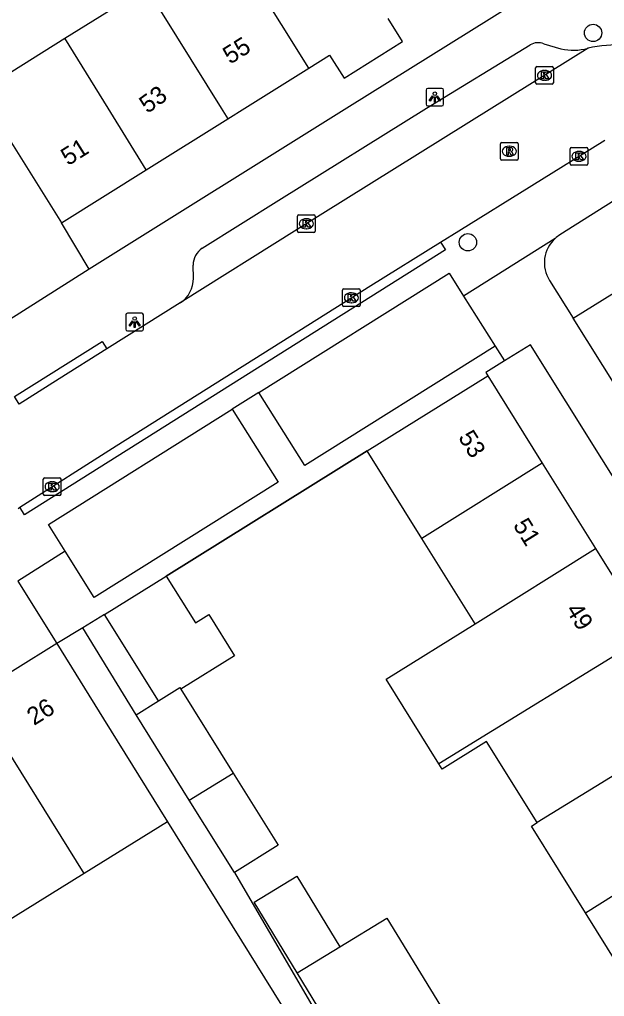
# Model space of a CAD drawing. Extents: x 157767 to 159171, y 387842 to 389425.
# Drawn here: x 158417.9 to 158451, y 388199.8 to 388255 of the extents above; entities that cross this region are included whole.
import ezdxf

# ---------------------------------------------------------------- set-up
doc = ezdxf.new("R2010")
doc.units = 0
for name, color, linetype in [('IMGEO_Boom', 7, 'Continuous'), ('IMGEO_Groenvoorziening', 7, 'Continuous'), ('IMGEO_Kolk', 7, 'Continuous'), ('IMGEO_Lichtpunt', 7, 'Continuous'), ('IMGEO_Muur', 7, 'Continuous'), ('IMGEO_Pand', 7, 'Continuous'), ('IMGEO_Pand_nummerreeks', 7, 'Continuous'), ('IMGEO_Rijbaan_lokaal_open', 7, 'Continuous'), ('IMGEO_Rioolput', 7, 'Continuous'), ('IMGEO_Voetpad_open', 7, 'Continuous')]:
    doc.layers.add(name, color=color, linetype=linetype)

msp = doc.modelspace()

# ---------------------------------------------------------------- linework, layer by layer
at = {"layer": 'IMGEO_Boom'}
for centre in [(158450.319, 388254.256), (158443.243, 388242.419)]:
    msp.add_circle(centre, 0.489, dxfattribs=at)
at = {"layer": 'IMGEO_Groenvoorziening'}
msp.add_lwpolyline([(158449.191, 388238.128), (158453.713, 388240.945), (158464.018, 388232.359)], dxfattribs=at)
at = {"layer": 'IMGEO_Kolk'}
for p, q in [((158447.072, 388251.429), (158447.072, 388252.281)), ((158447.147, 388252.355), (158447.999, 388252.355)), ((158447.56, 388252.135), (158447.585, 388252.135)), ((158448.073, 388252.281), (158448.073, 388251.429)), ((158447.583, 388251.575), (158447.558, 388251.575)), ((158447.999, 388251.355), (158447.147, 388251.355)), ((158449.02, 388246.852), (158449.02, 388247.704)), ((158449.095, 388247.778), (158449.947, 388247.778)), ((158449.508, 388247.558), (158449.533, 388247.558)), ((158450.021, 388247.704), (158450.021, 388246.852)), ((158449.531, 388246.998), (158449.506, 388246.998)), ((158449.947, 388246.778), (158449.095, 388246.778)), ((158433.622, 388243.041), (158433.622, 388243.893)), ((158433.697, 388243.967), (158434.549, 388243.967)), ((158434.11, 388243.747), (158434.135, 388243.747)), ((158434.623, 388243.893), (158434.623, 388243.041)), ((158434.133, 388243.187), (158434.108, 388243.187)), ((158434.549, 388242.967), (158433.697, 388242.967)), ((158436.242, 388239.783), (158437.094, 388239.783)), ((158436.167, 388238.857), (158436.167, 388239.709)), ((158436.655, 388239.563), (158436.68, 388239.563)), ((158437.168, 388239.709), (158437.168, 388238.857)), ((158437.094, 388238.783), (158436.242, 388238.783)), ((158436.678, 388239.003), (158436.653, 388239.003)), ((158419.264, 388228.177), (158419.264, 388229.029)), ((158419.339, 388229.103), (158420.191, 388229.103)), ((158419.752, 388228.883), (158419.777, 388228.883)), ((158420.265, 388229.029), (158420.265, 388228.177)), ((158419.775, 388228.323), (158419.75, 388228.323)), ((158420.191, 388228.103), (158419.339, 388228.103))]:
    msp.add_line(p, q, dxfattribs=at)
for points in [[(158447.072, 388251.429), (158447.072, 388252.281)], [(158447.147, 388252.355), (158447.999, 388252.355)], [(158447.393, 388252.055), (158447.516, 388252.055), (158447.516, 388251.904), (158447.646, 388252.055), (158447.81, 388252.055), (158447.664, 388251.904), (158447.817, 388251.655), (158447.665, 388251.655), (158447.58, 388251.819), (158447.516, 388251.752), (158447.516, 388251.655), (158447.393, 388251.655), (158447.393, 388252.055)], [(158448.073, 388252.281), (158448.073, 388251.429)], [(158447.999, 388251.355), (158447.147, 388251.355)], [(158449.02, 388246.852), (158449.02, 388247.704)], [(158449.095, 388247.778), (158449.947, 388247.778)], [(158450.021, 388247.704), (158450.021, 388246.852)], [(158449.341, 388247.478), (158449.464, 388247.478), (158449.464, 388247.327), (158449.594, 388247.478), (158449.758, 388247.478), (158449.612, 388247.327), (158449.765, 388247.078), (158449.613, 388247.078), (158449.528, 388247.242), (158449.464, 388247.175), (158449.464, 388247.078), (158449.341, 388247.078), (158449.341, 388247.478)], [(158449.947, 388246.778), (158449.095, 388246.778)], [(158433.622, 388243.041), (158433.622, 388243.893)], [(158433.697, 388243.967), (158434.549, 388243.967)], [(158433.943, 388243.667), (158434.066, 388243.667), (158434.066, 388243.516), (158434.196, 388243.667), (158434.36, 388243.667), (158434.214, 388243.516), (158434.367, 388243.267), (158434.215, 388243.267), (158434.13, 388243.431), (158434.066, 388243.364), (158434.066, 388243.267), (158433.943, 388243.267), (158433.943, 388243.667)], [(158434.623, 388243.893), (158434.623, 388243.041)], [(158434.549, 388242.967), (158433.697, 388242.967)], [(158436.242, 388239.783), (158437.094, 388239.783)], [(158436.167, 388238.857), (158436.167, 388239.709)], [(158436.488, 388239.483), (158436.611, 388239.483), (158436.611, 388239.332), (158436.741, 388239.483), (158436.905, 388239.483), (158436.759, 388239.332), (158436.912, 388239.083), (158436.76, 388239.083), (158436.675, 388239.247), (158436.611, 388239.18), (158436.611, 388239.083), (158436.488, 388239.083), (158436.488, 388239.483)], [(158437.168, 388239.709), (158437.168, 388238.857)], [(158437.094, 388238.783), (158436.242, 388238.783)], [(158419.264, 388228.177), (158419.264, 388229.029)], [(158419.339, 388229.103), (158420.191, 388229.103)], [(158419.585, 388228.803), (158419.708, 388228.803), (158419.708, 388228.652), (158419.838, 388228.803), (158420.002, 388228.803), (158419.856, 388228.652), (158420.009, 388228.403), (158419.857, 388228.403), (158419.772, 388228.567), (158419.708, 388228.5), (158419.708, 388228.403), (158419.585, 388228.403), (158419.585, 388228.803)], [(158420.265, 388229.029), (158420.265, 388228.177)], [(158420.191, 388228.103), (158419.339, 388228.103)]]:
    msp.add_lwpolyline(points, dxfattribs=at)
for centre, start, end in [((158447.149, 388252.279), 91.552, 178.448), ((158447.149, 388252.279), 91.552, 178.448), ((158447.997, 388252.279), 1.552, 88.448), ((158447.997, 388252.279), 1.552, 88.448), ((158447.149, 388251.431), 181.552, 268.448), ((158447.149, 388251.431), 181.552, 268.448), ((158447.997, 388251.431), 271.552, 358.448), ((158447.997, 388251.431), 271.552, 358.448), ((158449.097, 388247.702), 91.552, 178.448), ((158449.097, 388247.702), 91.552, 178.448), ((158449.945, 388247.702), 1.552, 88.448), ((158449.945, 388247.702), 1.552, 88.448), ((158449.097, 388246.854), 181.552, 268.448), ((158449.097, 388246.854), 181.552, 268.448), ((158449.945, 388246.854), 271.552, 358.448), ((158449.945, 388246.854), 271.552, 358.448), ((158433.699, 388243.891), 91.552, 178.448), ((158433.699, 388243.891), 91.552, 178.448), ((158434.547, 388243.891), 1.552, 88.448), ((158434.547, 388243.891), 1.552, 88.448), ((158433.699, 388243.043), 181.552, 268.448), ((158433.699, 388243.043), 181.552, 268.448), ((158434.547, 388243.043), 271.552, 358.448), ((158434.547, 388243.043), 271.552, 358.448), ((158436.244, 388239.707), 91.552, 178.448), ((158436.244, 388239.707), 91.552, 178.448), ((158437.092, 388239.707), 1.552, 88.448), ((158437.092, 388239.707), 1.552, 88.448), ((158436.244, 388238.859), 181.552, 268.448), ((158436.244, 388238.859), 181.552, 268.448), ((158437.092, 388238.859), 271.552, 358.448), ((158437.092, 388238.859), 271.552, 358.448), ((158419.341, 388229.027), 91.552, 178.448), ((158419.341, 388229.027), 91.552, 178.448), ((158420.189, 388229.027), 1.552, 88.448), ((158420.189, 388229.027), 1.552, 88.448), ((158419.341, 388228.179), 181.552, 268.448), ((158419.341, 388228.179), 181.552, 268.448), ((158420.189, 388228.179), 271.552, 358.448), ((158420.189, 388228.179), 271.552, 358.448)]:
    msp.add_arc(centre, 0.0765, start, end, dxfattribs=at)
for centre, major_axis, ratio, start_param, end_param in [((158447.559, 388251.855), (-0.387, 0.002), 0.722429, 4.712389, 7.853982), ((158447.584, 388251.855), (-0.39, 0.002), 0.717154, 1.570796, 4.712389), ((158449.507, 388247.278), (-0.387, 0.002), 0.722429, 4.712389, 7.853982), ((158449.532, 388247.278), (-0.39, 0.002), 0.717154, 1.570796, 4.712389), ((158434.109, 388243.467), (-0.387, 0.002), 0.722429, 4.712389, 7.853982), ((158434.134, 388243.467), (-0.39, 0.002), 0.717154, 1.570796, 4.712389), ((158436.654, 388239.283), (-0.387, 0.002), 0.722429, 4.712389, 7.853982), ((158436.679, 388239.283), (-0.39, 0.002), 0.717154, 1.570796, 4.712389), ((158419.751, 388228.603), (-0.387, 0.002), 0.722429, 4.712389, 7.853982), ((158419.776, 388228.603), (-0.39, 0.002), 0.717154, 1.570796, 4.712389)]:
    msp.add_ellipse(centre, major_axis=major_axis, ratio=ratio, start_param=start_param, end_param=end_param, dxfattribs=at)
at = {"layer": 'IMGEO_Lichtpunt'}
for p, q in [((158440.88, 388251.027), (158440.88, 388250.22)), ((158440.88, 388251.027), (158440.88, 388250.22)), ((158441.782, 388251.122), (158440.974, 388251.122)), ((158441.782, 388251.122), (158440.974, 388251.122)), ((158441.876, 388250.22), (158441.876, 388251.027)), ((158441.876, 388250.22), (158441.876, 388251.027)), ((158440.974, 388250.126), (158441.782, 388250.126)), ((158440.974, 388250.126), (158441.782, 388250.126)), ((158423.927, 388238.312), (158423.927, 388237.505)), ((158423.927, 388238.312), (158423.927, 388237.505)), ((158424.829, 388238.407), (158424.021, 388238.407)), ((158424.829, 388238.407), (158424.021, 388238.407)), ((158424.923, 388237.505), (158424.923, 388238.312)), ((158424.923, 388237.505), (158424.923, 388238.312)), ((158424.021, 388237.411), (158424.829, 388237.411)), ((158424.021, 388237.411), (158424.829, 388237.411))]:
    msp.add_line(p, q, dxfattribs=at)
for points in [[(158441.254, 388250.691), (158441.293, 388250.663), (158441.105, 388250.401), (158441.067, 388250.428), (158441.254, 388250.691)], [(158441.356, 388250.643), (158441.403, 388250.643), (158441.403, 388250.321), (158441.356, 388250.321), (158441.356, 388250.643)], [(158441.466, 388250.663), (158441.504, 388250.69), (158441.691, 388250.428), (158441.652, 388250.4), (158441.466, 388250.663)], [(158424.301, 388237.976), (158424.34, 388237.948), (158424.152, 388237.686), (158424.114, 388237.713), (158424.301, 388237.976)], [(158424.403, 388237.928), (158424.45, 388237.928), (158424.45, 388237.606), (158424.403, 388237.606), (158424.403, 388237.928)], [(158424.513, 388237.948), (158424.551, 388237.975), (158424.738, 388237.713), (158424.699, 388237.685), (158424.513, 388237.948)]]:
    msp.add_lwpolyline(points, dxfattribs=at)
for centre in [(158441.379, 388250.825), (158424.426, 388238.11)]:
    msp.add_circle(centre, 0.0994, dxfattribs=at)
for centre, start, end in [((158440.974, 388251.027), 90, 180), ((158440.974, 388251.027), 90, 180), ((158441.782, 388251.027), 0, 90), ((158441.782, 388251.027), 0, 90), ((158440.974, 388250.22), 180, 270), ((158440.974, 388250.22), 180, 270), ((158441.782, 388250.22), 270, 0), ((158441.782, 388250.22), 270, 360), ((158424.021, 388238.312), 90, 180), ((158424.021, 388238.312), 90, 180), ((158424.829, 388238.312), 0, 90), ((158424.829, 388238.312), 0, 90), ((158424.021, 388237.505), 180, 270), ((158424.021, 388237.505), 180, 270), ((158424.829, 388237.505), 270, 0), ((158424.829, 388237.505), 270, 360)]:
    msp.add_arc(centre, 0.0946, start, end, dxfattribs=at)
at = {"layer": 'IMGEO_Muur'}
msp.add_lwpolyline([(158426.209, 388223.555), (158437.564, 388230.626)], dxfattribs=at)
at = {"layer": 'IMGEO_Pand'}
for points in [[(158434.257, 388252.266), (158429.634, 388259.687)], [(158420.487, 388253.952), (158425.074, 388256.828)], [(158425.074, 388256.828), (158429.309, 388250), (158429.683, 388249.398)], [(158434.257, 388252.266), (158435.432, 388253.003), (158436.25, 388251.698), (158439.554, 388253.77), (158438.736, 388255.075)], [(158415.649, 388250.918), (158420.487, 388253.952)], [(158425.084, 388246.515), (158422.93, 388250), (158420.487, 388253.952)], [(158429.683, 388249.398), (158430.642, 388250), (158434.257, 388252.266)], [(158415.649, 388250.918), (158416.225, 388250), (158420.293, 388243.511)], [(158425.084, 388246.515), (158429.683, 388249.398)], [(158420.293, 388243.511), (158425.084, 388246.515)], [(158437.564, 388230.626), (158444.372, 388234.867)], [(158444.372, 388234.867), (158447.444, 388229.936)], [(158440.642, 388225.684), (158437.564, 388230.626)], [(158447.444, 388229.936), (158440.642, 388225.684)], [(158447.444, 388229.936), (158450.447, 388225.115)], [(158443.654, 388220.849), (158440.642, 388225.684)], [(158443.654, 388220.849), (158450.447, 388225.115)], [(158450.447, 388225.115), (158453.477, 388220.252)], [(158422.73, 388221.386), (158426.209, 388223.555)], [(158426.209, 388223.555), (158427.855, 388220.914), (158428.61, 388221.384), (158430.064, 388219.05), (158427.035, 388217.163)], [(158425.778, 388216.497), (158422.73, 388221.386)], [(158441.607, 388212.94), (158438.63, 388217.72), (158443.654, 388220.849)], [(158453.477, 388220.252), (158441.607, 388212.94)], [(158420.027, 388219.737), (158415.31, 388216.807)], [(158420.027, 388219.737), (158422.666, 388215.49), (158426.285, 388209.663)], [(158425.778, 388216.497), (158426.984, 388217.245), (158427.035, 388217.163)], [(158427.035, 388217.163), (158429.995, 388212.412)], [(158421.577, 388206.738), (158415.31, 388216.807)], [(158424.503, 388215.703), (158425.778, 388216.497)], [(158427.51, 388210.877), (158424.503, 388215.703)], [(158456.522, 388215.363), (158447.153, 388209.614)], [(158447.153, 388209.614), (158444.3, 388214.195), (158441.796, 388212.636), (158441.607, 388212.94)], [(158427.51, 388210.877), (158429.995, 388212.412)], [(158429.995, 388212.412), (158432.534, 388208.336), (158430.055, 388206.791)], [(158430.055, 388206.791), (158427.51, 388210.877)], [(158449.894, 388204.509), (158459.089, 388210.297)], [(158426.285, 388209.663), (158421.577, 388206.738)], [(158449.894, 388204.509), (158446.837, 388209.417), (158447.153, 388209.614)], [(158421.577, 388206.738), (158417.003, 388203.897)], [(158433.6, 388201.125), (158431.17, 388205.112), (158433.585, 388206.583), (158436.015, 388202.596)], [(158452.904, 388199.677), (158449.894, 388204.509)], [(158436.015, 388202.596), (158438.669, 388204.213), (158441.69, 388199.255), (158439.327, 388197.816), (158439.495, 388197.541), (158436.788, 388195.891), (158433.6, 388201.125)], [(158433.6, 388201.125), (158436.015, 388202.596)]]:
    msp.add_lwpolyline(points, dxfattribs=at)
at = {"layer": 'IMGEO_Rijbaan_lokaal_open'}
for points in [[(158450.03, 388253.386), (158444.601, 388250), (158433.601, 388243.14), (158426.997, 388238.989)], [(158441.705, 388242.421), (158442.729, 388243.058), (158450.978, 388248.185)], [(158421.862, 388240.906), (158420.293, 388243.511)], [(158417.945, 388227.442), (158423.385, 388230.907), (158437.76, 388239.969), (158441.705, 388242.421)], [(158421.862, 388240.906), (158415.402, 388236.809)], [(158426.997, 388238.989), (158422.86, 388236.388)], [(158422.86, 388236.388), (158420.167, 388234.695), (158417.904, 388233.275)], [(158417.846, 388227.379), (158417.945, 388227.442)]]:
    msp.add_lwpolyline(points, dxfattribs=at)
msp.add_arc((158451.851, 388245.243), 8.345, 88.2067, 102.6039, dxfattribs=at)
at = {"layer": 'IMGEO_Rioolput'}
for p, q in [((158445.16, 388248.066), (158446.012, 388248.066)), ((158445.085, 388247.14), (158445.085, 388247.992)), ((158445.573, 388247.846), (158445.598, 388247.846)), ((158446.086, 388247.992), (158446.086, 388247.14)), ((158446.012, 388247.066), (158445.16, 388247.066)), ((158445.596, 388247.286), (158445.571, 388247.286))]:
    msp.add_line(p, q, dxfattribs=at)
for points in [[(158445.16, 388248.066), (158446.012, 388248.066)], [(158445.085, 388247.14), (158445.085, 388247.992)], [(158445.674, 388247.764), (158445.422, 388247.766), (158445.422, 388247.366)], [(158445.422, 388247.366), (158445.546, 388247.366), (158445.546, 388247.528), (158445.557, 388247.528)], [(158445.6, 388247.685), (158445.546, 388247.685), (158445.546, 388247.604)], [(158445.546, 388247.604), (158445.598, 388247.604)], [(158445.604, 388247.499), (158445.675, 388247.366), (158445.815, 388247.366), (158445.75, 388247.492)], [(158446.086, 388247.992), (158446.086, 388247.14)], [(158446.012, 388247.066), (158445.16, 388247.066)]]:
    msp.add_lwpolyline(points, dxfattribs=at)
for centre, radius, start, end in [((158445.162, 388247.99), 0.0765, 91.552, 178.448), ((158445.162, 388247.99), 0.0765, 91.552, 178.448), ((158446.01, 388247.99), 0.0765, 1.552, 88.448), ((158446.01, 388247.99), 0.0765, 1.552, 88.448), ((158445.556, 388247.475), 0.0533, 26.0293, 88.6989), ((158445.582, 388247.793), 0.19, 274.7715, 282.9687), ((158445.606, 388247.589), 0.0964, 77.0061, 93.1865), ((158445.62, 388247.646), 0.0378, 276.6634, 79.6772), ((158445.673, 388247.654), 0.109, 350.3612, 89.416), ((158445.671, 388247.654), 0.112, 277.5842, 350.9817), ((158445.655, 388247.439), 0.108, 29.5134, 73.7905), ((158445.162, 388247.142), 0.0765, 181.552, 268.448), ((158445.162, 388247.142), 0.0765, 181.552, 268.448), ((158446.01, 388247.142), 0.0765, 271.552, 358.448), ((158446.01, 388247.142), 0.0765, 271.552, 358.448)]:
    msp.add_arc(centre, radius, start, end, dxfattribs=at)
for centre, major_axis, ratio, start_param, end_param in [((158445.572, 388247.566), (-0.387, 0.002), 0.722429, 4.712389, 7.853982), ((158445.597, 388247.566), (-0.39, 0.002), 0.717154, 1.570796, 4.712389)]:
    msp.add_ellipse(centre, major_axis=major_axis, ratio=ratio, start_param=start_param, end_param=end_param, dxfattribs=at)
at = {"layer": 'IMGEO_Voetpad_open'}
for points in [[(158452.643, 388260.147), (158436.41, 388250), (158421.862, 388240.906)], [(158428.245, 388242.081), (158432.564, 388244.796), (158440.91, 388250), (158446.764, 388253.576)], [(158447.543, 388253.641), (158448.502, 388253.348)], [(158454.856, 388246.9), (158448.432, 388242.838)], [(158448.173, 388242.641), (158442.999, 388239.378)], [(158441.705, 388242.421), (158441.971, 388241.999), (158418.211, 388227.02), (158417.945, 388227.442)], [(158427.741, 388240.391), (158427.731, 388241.135)], [(158431.443, 388233.93), (158442.186, 388240.674), (158442.999, 388239.378)], [(158447.856, 388240.259), (158449.191, 388238.128)], [(158442.999, 388239.378), (158444.776, 388236.547)], [(158455.004, 388228.847), (158449.191, 388238.128)], [(158417.904, 388233.275), (158417.639, 388233.698), (158422.595, 388236.811), (158422.86, 388236.388)], [(158444.776, 388236.547), (158434.034, 388229.803), (158431.443, 388233.93)], [(158444.776, 388236.547), (158445.308, 388235.71)], [(158479.339, 388184.502), (158477.28, 388187.843), (158446.777, 388236.625), (158445.308, 388235.71)], [(158445.308, 388235.71), (158444.255, 388235.054), (158444.372, 388234.867)], [(158431.443, 388233.93), (158429.933, 388232.982)], [(158420.5, 388224.955), (158419.552, 388226.465), (158429.933, 388232.982)], [(158429.933, 388232.982), (158432.524, 388228.855), (158422.142, 388222.339), (158420.5, 388224.955)], [(158437.564, 388230.626), (158426.209, 388223.555)], [(158420.5, 388224.955), (158417.818, 388223.257)], [(158417.818, 388223.257), (158420.027, 388219.737)], [(158422.73, 388221.386), (158421.495, 388220.633)], [(158421.495, 388220.633), (158420.027, 388219.737)], [(158424.503, 388215.703), (158421.495, 388220.633)], [(158426.285, 388209.663), (158432.727, 388199.29)], [(158430.055, 388206.791), (158436.36, 388195.992)]]:
    msp.add_lwpolyline(points, dxfattribs=at)
for centre, radius, start, end in [((158447.218, 388252.835), 0.869, 68.0561, 121.4834), ((158449.187, 388256.529), 3.254, 257.8406, 285.0086), ((158449.428, 388241.262), 1.864, 132.2943, 212.5448), ((158449.429, 388241.259), 1.867, 122.2586, 132.2559), ((158428.829, 388241.151), 1.098, 122.1388, 180.8272), ((158426.092, 388240.368), 1.649, 303.2774, 0.8155)]:
    msp.add_arc(centre, radius, start, end, dxfattribs=at)

# ---------------------------------------------------------------- texts
at = {"layer": 'IMGEO_Pand_nummerreeks'}
for s, rotation, p in [('55', 32.0856, (158429.812, 388252.455)), ('53', 35.8168, (158425.146, 388249.668)), ('51', 32.0875, (158420.662, 388246.717)), ('53', 301.9208, (158442.669, 388231.397)), ('51', 301.9208, (158445.767, 388226.425)), ('49', 301.9208, (158448.744, 388221.645)), ('26', 31.8496, (158418.739, 388215.076))]:
    msp.add_text(s, height=1, rotation=rotation, dxfattribs=at).set_placement(p)

doc.saveas('drawing.dxf')
